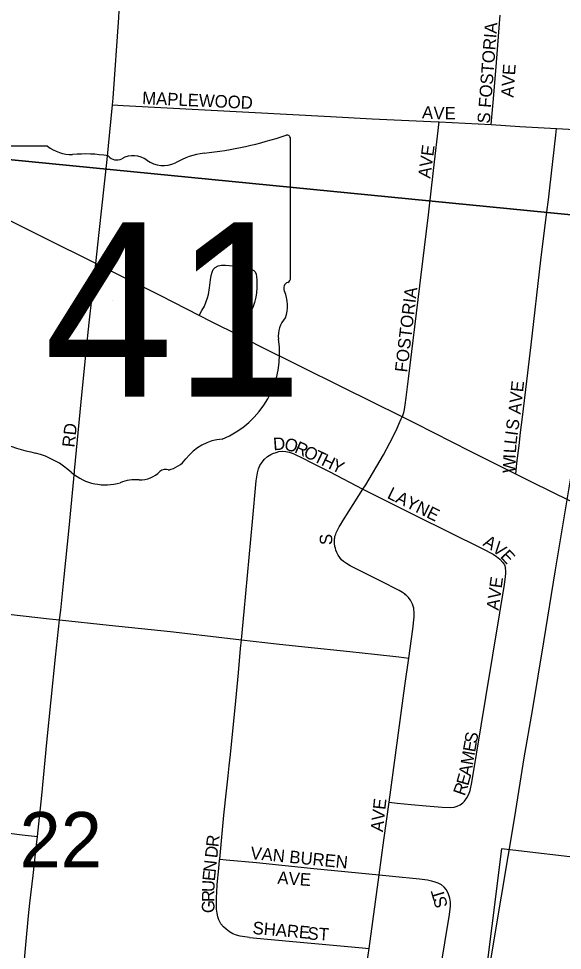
# Model space of a CAD drawing. Extents: x 1410790 to 1770854, y 566777 to 831614.
# Drawn here: x 1612046 to 1614218, y 699284 to 703004 of the extents above; entities that cross this region are included whole.
import ezdxf

# ---------------------------------------------------------------- set-up
doc = ezdxf.new("R2010")
doc.units = 0
for name, color, linetype in [('GM_X_City_Street', 7, 'Continuous'), ('GM_X_City_Street_Text', 7, 'Continuous'), ('GM_X_Corporation', 7, 'Continuous'), ('GM_X_Rail_Line', 7, 'Continuous'), ('GM_X_Section', 7, 'Continuous'), ('GM_X_Section_Text', 7, 'Continuous'), ('GM_X_State_Location', 7, 'Continuous'), ('GM_X_State_Route', 7, 'Continuous'), ('GM_X_State_Shield', 7, 'Continuous')]:
    doc.layers.add(name, color=color, linetype=linetype)

msp = doc.modelspace()

# ---------------------------------------------------------------- linework, layer by layer
at = {"layer": 'GM_X_City_Street'}
for points in [[(1612421.4, 702660), (1612424, 702686.5), (1612446.4, 703007.9), (1612447.3, 703035.5)], [(1613933.3, 702580.7), (1613942.7, 702683.4), (1613955.5, 702829.3), (1613967, 702984.5), (1613969.5, 703017.3)], [(1612354.1, 702026.6), (1612367.5, 702149.5), (1612399.5, 702441.7), (1612421.4, 702660)], [(1612421.4, 702660), (1612463.6, 702657.8), (1613291.4, 702613.7), (1613458.7, 702604.4), (1613722, 702592), (1613726.7, 702591.7)], [(1613578, 701413.5), (1613579.1, 701415.9), (1613584.5, 701431.2), (1613587.7, 701443.4), (1613590.3, 701461.9), (1613594.4, 701491.6), (1613603, 701565.5), (1613667.2, 702090.3), (1613683.5, 702220.2), (1613703.9, 702398.3), (1613726.7, 702591.7)], [(1613726.7, 702591.7), (1613933.3, 702580.7)], [(1613933.3, 702580.7), (1614048.3, 702573.3), (1614195, 702565.2)], [(1614032.6, 701185), (1614036.8, 701229.3), (1614045.2, 701299.2), (1614051.4, 701352.2), (1614058.6, 701412.3), (1614076.2, 701556.8), (1614093.6, 701701.8), (1614132.7, 702039.7), (1614156.6, 702232.7), (1614162.5, 702280.6), (1614168.2, 702328.5), (1614192, 702539.1), (1614195, 702565.2)], [(1614195, 702565.2), (1614290.8, 702559.9), (1614439.8, 702552.4)], [(1612268.9, 701194.1), (1612269.2, 701198.2), (1612295.6, 701474.5), (1612316.5, 701675.6), (1612327.9, 701789.6), (1612351.4, 702002.1), (1612354.1, 702026.6)], [(1612767.2, 701819), (1612778.1, 701838.4), (1612788.1, 701856), (1612795.7, 701874.1), (1612800.7, 701889.3), (1612804.5, 701902.9), (1612808.4, 701928.9), (1612812.3, 701961.4), (1612814.8, 701977.9), (1612818.7, 701991.1), (1612823.4, 702002.5), (1612831.1, 702010.8), (1612842.7, 702017.1), (1612856.6, 702019.6), (1612872.7, 702020), (1612901.9, 702017.1), (1612936.2, 702012.8), (1612959.4, 702008.6), (1612973, 702005.4), (1612985.2, 701998.9), (1612991.2, 701992.5), (1612994.8, 701983.9), (1612996.6, 701972.5), (1612997.7, 701960.7), (1612997.7, 701944.6), (1612997.3, 701928.9), (1612995.9, 701909.7), (1612993.4, 701891.8), (1612988.2, 701870.4), (1612983.2, 701854.2), (1612971.7, 701828.5), (1612927.1, 701738.9)], [(1613421.8, 701124.7), (1613433.3, 701142.7), (1613503.6, 701262.8), (1613529.7, 701311), (1613555.1, 701361.7), (1613565.5, 701384.3), (1613574.6, 701405.6), (1613578, 701413.5)], [(1612935.9, 700523.7), (1612947.3, 700636.4), (1612980.2, 700996.7), (1612995, 701159.1), (1613000.1, 701191), (1613004.3, 701206.2), (1613010.2, 701220.4), (1613018.6, 701233.6), (1613028.9, 701245.4), (1613040.7, 701255.5), (1613054, 701263.5), (1613061.6, 701267.1)], [(1613061.6, 701267.1), (1613074.9, 701271.9), (1613086.2, 701275.1), (1613100.1, 701277), (1613113, 701276.2), (1613127.2, 701273.1), (1613142.6, 701267.4), (1613186.9, 701246.7), (1613206.8, 701236.3), (1613289.1, 701194.1), (1613421.8, 701124.7)], [(1612210.1, 700603.7), (1612214.4, 700642.2), (1612228, 700774.8), (1612247.6, 700970.6), (1612268.9, 701194.1)], [(1613309.6, 700896.9), (1613308.2, 700908.4), (1613307.8, 700916.9), (1613307.8, 700922.1), (1613308.1, 700926.7), (1613308.7, 700930.8), (1613309.9, 700936.5), (1613311, 700940.5), (1613313, 700946), (1613315.3, 700951.2), (1613317.2, 700955.7), (1613320.1, 700961.6), (1613327.1, 700974.8), (1613331.6, 700982.9), (1613341.6, 700999.2), (1613366.8, 701038.2), (1613421.8, 701124.7)], [(1613421.8, 701124.7), (1613445.5, 701113), (1613631.2, 701020.8), (1613897.9, 700888.8), (1613941.7, 700865.3), (1613955.5, 700856.2), (1613968.2, 700845.9), (1613979, 700834.3), (1613986.7, 700822.9), (1613991.7, 700810.1)], [(1613605, 700451.2), (1613620.9, 700566.5), (1613626.2, 700616), (1613626.3, 700627), (1613625.9, 700635.7), (1613625.2, 700643.7), (1613624.3, 700649.6), (1613622.3, 700658.1), (1613619.6, 700666.3), (1613616.1, 700673.9), (1613611.4, 700681.7), (1613606.3, 700689), (1613603, 700693.1), (1613599.3, 700697.3), (1613595.4, 700701), (1613592, 700703.9), (1613588.5, 700706.9), (1613583.6, 700710.3), (1613579.7, 700713), (1613573.4, 700716.8), (1613567, 700720.4), (1613558.5, 700724.8), (1613501.2, 700754), (1613370.4, 700818.9), (1613355.4, 700828.1), (1613344.2, 700836.2), (1613336.2, 700843.6), (1613328.9, 700852.5), (1613322.4, 700862.3), (1613317.5, 700872), (1613313.5, 700882.2), (1613311.4, 700889.7), (1613309.6, 700896.9)], [(1613820.3, 699872.4), (1613827.6, 699879.4), (1613837.1, 699892.6), (1613844.2, 699907.3), (1613849.5, 699922.6), (1613857, 699954.4), (1613912.8, 700293.2), (1613969, 700631.6), (1613986.6, 700744.6), (1613989.7, 700764.9), (1613992.2, 700788.8), (1613992.7, 700799.5), (1613991.7, 700810.1)], [(1611723.6, 700656), (1611853, 700643.9), (1612170, 700608), (1612210.1, 700603.7)], [(1612121.5, 699738.3), (1612138.9, 699902.7), (1612159.3, 700113.7), (1612193.1, 700454.3), (1612210.1, 700603.7)], [(1612210.1, 700603.7), (1612407.8, 700582.4), (1612652.8, 700556.9), (1612881, 700529.9), (1612935.9, 700523.7)], [(1612849.5, 699648.4), (1612866.2, 699823.3), (1612876.6, 699920.6), (1612883.1, 699981.1), (1612887.3, 700020.1), (1612892.2, 700066.5), (1612901, 700147.6), (1612910.9, 700252.7), (1612924, 700391.5), (1612932.8, 700489.1), (1612935.9, 700523.7)], [(1612935.9, 700523.7), (1613076.1, 700507.9), (1613190.1, 700495.6), (1613369.7, 700476.9), (1613467.6, 700466.8), (1613565.4, 700455.7), (1613605, 700451.2)], [(1613526.2, 699875.4), (1613589.6, 700339.6), (1613605, 700451.2)], [(1613486.7, 699585.8), (1613505.4, 699723.4), (1613526.2, 699875.4)], [(1613526.2, 699875.4), (1613558.5, 699872.3), (1613614.9, 699867), (1613674.8, 699861), (1613738.4, 699855.5), (1613772.2, 699854.8), (1613785.5, 699855.9), (1613798.7, 699859.5), (1613809.8, 699864.8), (1613820.3, 699872.4)], [(1611832.5, 699773.6), (1611882, 699767.6), (1612060.9, 699745.8), (1612121.5, 699738.3)], [(1612114.1, 699670), (1612118, 699705.3), (1612121.5, 699738.3)], [(1612059.8, 699144.5), (1612062.8, 699175.6), (1612085.8, 699421.4), (1612091, 699471.9), (1612104.5, 699582.9), (1612114.1, 699670)], [(1612969.1, 699335.1), (1612931.7, 699340.4), (1612916.4, 699344.4), (1612902, 699350.2), (1612888.5, 699358.1), (1612875.2, 699368.2), (1612864.3, 699378.5), (1612854.4, 699390.4), (1612846.6, 699405.5), (1612842.1, 699418.5), (1612838.8, 699432.4), (1612837, 699448), (1612836.2, 699465.5), (1612837, 699496.7), (1612837.7, 699514.8), (1612839.6, 699546.9), (1612845.7, 699610.4), (1612848.9, 699644.4), (1612849.5, 699648.4)], [(1612849.5, 699648.4), (1612875.2, 699646), (1612996.7, 699634.7), (1613225.1, 699611.3), (1613486.7, 699585.8)], [(1613446.3, 699292), (1613486.7, 699585.8)], [(1613486.7, 699585.8), (1613539.2, 699580.7), (1613647.7, 699569.5), (1613679.7, 699565.3), (1613695.2, 699561.9), (1613709.2, 699557.9), (1613720.7, 699553.3), (1613733.7, 699546.4), (1613745.7, 699536.9)], [(1613646.2, 698696.7), (1613669, 698829), (1613693.1, 698973.9), (1613719.3, 699135.8), (1613749.2, 699313.7), (1613767.9, 699427.2), (1613771.1, 699459.9), (1613771.1, 699476.2), (1613769, 699492.3), (1613764, 699507.9), (1613760.1, 699518.2), (1613753.5, 699526.9), (1613745.7, 699536.9)], [(1612969.1, 699335.1), (1613156.8, 699317.7), (1613420.4, 699294.4), (1613446.3, 699292)], [(1613357.1, 699022.1), (1613390.1, 699064.4), (1613397.2, 699074.8), (1613409, 699092.2), (1613413, 699099.6), (1613416.3, 699107.1), (1613419.5, 699115.9), (1613422, 699125.9), (1613424.8, 699138.8), (1613427.4, 699153.3), (1613439.1, 699238.8), (1613446.3, 699292)]]:
    msp.add_lwpolyline(points, dxfattribs=at)
at = {"layer": 'GM_X_Corporation'}
msp.add_lwpolyline([(1616305.8, 699835.5), (1615832.7, 699882.7), (1615779.1, 699374.7), (1614920.1, 699465.3), (1614931, 699590.3), (1614738, 699606.3), (1614338.8, 699647.1), (1613974.6, 699689), (1613706.5, 697548.1), (1615532, 697360.8), (1616779.5, 697219.4)], dxfattribs=at)
at = {"layer": 'GM_X_Rail_Line'}
msp.add_lwpolyline([(1613660.2, 697611.3), (1613756.8, 698189.3), (1613762.8, 698225.7), (1613816.6, 698552.5), (1613852, 698764.6), (1613897.7, 699037.2), (1613949, 699342.4), (1613974.5, 699500.6), (1614028, 699817.5), (1614066.2, 700052.9), (1614098.4, 700241.6), (1614144.5, 700515.3), (1614191.5, 700803.5), (1614239.3, 701090.6), (1614274, 701298.4), (1614314.4, 701537.4), (1614347, 701737.4), (1614371, 701881.5), (1614402.2, 702071.6), (1614437.6, 702281.5), (1614491, 702600.5), (1614533.2, 702850.1), (1614561.1, 703019.8)], dxfattribs=at)
at = {"layer": 'GM_X_Section'}
for points in [[(1610104.6, 708025.3), (1615479.9, 707495.5), (1615120.2, 702135.6), (1609553.2, 702682.3)], [(1609553.2, 702682.3), (1615120.2, 702135.6), (1614682.3, 696901), (1609051.7, 697468.6)]]:
    msp.add_lwpolyline(points, close=True, dxfattribs=at)
at = {"layer": 'GM_X_State_Route'}
msp.add_lwpolyline([(1614552.2, 700924.3), (1614395.4, 701003.4), (1614247.9, 701078.9), (1614099.4, 701151.8), (1614032.6, 701185), (1613851.2, 701276), (1613631.5, 701387.1), (1613578, 701413.5), (1613338.1, 701532.9), (1613006.1, 701697.7), (1612927.1, 701738.9), (1612816.7, 701793.8), (1612767.2, 701819), (1612614.2, 701896.7), (1612354.1, 702026.6), (1612148, 702129.3), (1611849.9, 702278.1)], dxfattribs=at)
at = {"layer": 'GM_X_State_Shield'}
for p, q in [((1612161.7, 702495.3), (1611754, 702495.3)), ((1613132.5, 701968.8), (1613132.5, 702521.5)), ((1613132.4, 701968.9), (1613132.5, 701968.8))]:
    msp.add_line(p, q, dxfattribs=at)
for centre, radius, start, end in [((1612636.6, 703935.9), 1476.4, 275.8445, 288.9065), ((1613117, 702523.8), 15.5, 351.8621, 97.738), ((1612258.8, 702618), 156.4, 231.6195, 271.1119), ((1612310.7, 701902.1), 561.6, 80.4867, 94.9883), ((1612824.9, 702172.6), 297, 97.3462, 120.7689), ((1612438.2, 702484.9), 45.1, 219.7921, 297.1024), ((1612504.4, 702362.8), 93.8, 54.4667, 119.1411), ((1612625.5, 702530.3), 112.9, 233.8562, 294.8282), ((1613128.9, 701928.2), 24, 107.944, 210.337), ((1613116, 701966.7), 16.6, 289.6038, 7.7341), ((1612976.3, 701858.3), 144, 340.033, 23.6496), ((1613188, 701737.5), 104.8, 136.8065, 186.9296), ((1612719.3, 701667.2), 369.3, 292.3089, 8.9858), ((1612349.6, 702308.9), 1066.1, 240.4129, 257.1985), ((1612875, 701123.9), 202.2, 94.4031, 142.5768), ((1612031.7, 700945.8), 333.6, 47.1842, 75.836), ((1612618.7, 701318.1), 119.3, 282.8732, 323.2771), ((1612530.3, 701275.2), 112.8, 268.777, 315.5493), ((1612632.3, 701172.9), 31.8, 65.7517, 132.6484), ((1612392.5, 701354.3), 211.7, 230.7004, 286.2918), ((1612514.8, 700989), 173.9, 85.6951, 111.2099)]:
    msp.add_arc(centre, radius, start, end, dxfattribs=at)

# ---------------------------------------------------------------- texts
at = {"layer": 'GM_X_City_Street_Text'}
for s, rotation, p in [('S FOSTORIA', 85.6552, (1613928.3, 702583.8)), ('AVE', 86.0571, (1614022.9, 702687.9)), ('MAPLEWOOD', 357.4554, (1612538.9, 702662.9)), ('A', 356.5123, (1613656.7, 702605.7)), ('V', 357.983, (1613702, 702603)), ('E', 359.9073, (1613747.8, 702601.4)), ('AVE', 82.4092, (1613690.8, 702364.2)), ('FOSTORIA', 83.1914, (1613598.4, 701589.9)), ('AVE', 83.8878, (1614051.6, 701422.5)), ('RD', 83.9946, (1612269.5, 701290.5)), ('S', 82.2447, (1614042, 701358.5)), ('I', 82.3274, (1614039.1, 701336.7)), ('D', 4.3208, (1613064.7, 701280.2)), ('O', 345.0094, (1613104.2, 701284)), ('R', 335.7811, (1613144.7, 701273.3)), ('L', 83.1529, (1614034.9, 701301.9)), ('O', 334.3637, (1613180.5, 701257.2)), ('T', 334.3657, (1613220.2, 701238.1)), ('L', 86.4185, (1614032.8, 701267.6)), ('H', 334.383, (1613251.9, 701222.9)), ('Y', 334.3637, (1613291.6, 701203.9)), ('W', 87.6287, (1614029.5, 701188.7)), ('I', 87.6358, (1614031.9, 701245.9)), ('LAYNE', 333.8859, (1613515, 701091.2)), ('S', 90, (1613299.1, 700902.3)), ('A', 329.6979, (1613897.9, 700902)), ('V', 321.5518, (1613934.3, 700880.9)), ('E', 313.3287, (1613967.4, 700854.8)), ('AVE', 82.1508, (1613963.6, 700639.6)), ('S', 79.9149, (1613875.9, 700107.7)), ('E', 79.92, (1613869.7, 700073.1)), ('M', 79.9421, (1613860.5, 700021.1)), ('A', 79.6208, (1613852.5, 699977.5)), ('E', 74.4027, (1613841.9, 699938.8)), ('R', 70.5936, (1613827.7, 699898)), ('AVE', 83.8878, (1613501.5, 699755)), ('R', 83.7952, (1612844.2, 699694.6)), ('D', 83.8074, (1612839.5, 699650.8)), ('VAN BUREN', 354.3597, (1612970.6, 699648.9)), ('N', 83.8022, (1612833.3, 699593.9)), ('E', 84.3356, (1612829.9, 699559)), ('AVE', 356.0531, (1613078.8, 699549.9)), ('U', 88.0108, (1612828.4, 699515.9)), ('R', 89.9228, (1612828.3, 699476.7)), ('T', 106.5179, (1613751.6, 699495.2)), ('S', 106.0542, (1613761.5, 699461)), ('G', 89.9126, (1612828.3, 699432.7)), ('SHARE', 355.0308, (1612979.3, 699349.7)), ('ST', 356.4262, (1613199.1, 699327.7))]:
    msp.add_text(s, height=50, rotation=rotation, dxfattribs=at).set_placement(p)
at = {"layer": 'GM_X_Section_Text'}
msp.add_text('22', height=221, rotation=0, dxfattribs=at).set_placement((1612050.1, 699615.1))
at = {"layer": 'GM_X_State_Location'}
for s in ['s', 'r']:
    msp.add_text(s, height=1, dxfattribs=at).set_placement((1612420.7, 701878.6))
msp.add_text('41', height=1, rotation=0, dxfattribs=at).set_placement((1612168.9, 701805.8))
at = {"layer": 'GM_X_State_Shield'}
msp.add_text('41', height=696.1, dxfattribs=at).set_placement((1612147.6, 701495))

doc.saveas('drawing.dxf')
